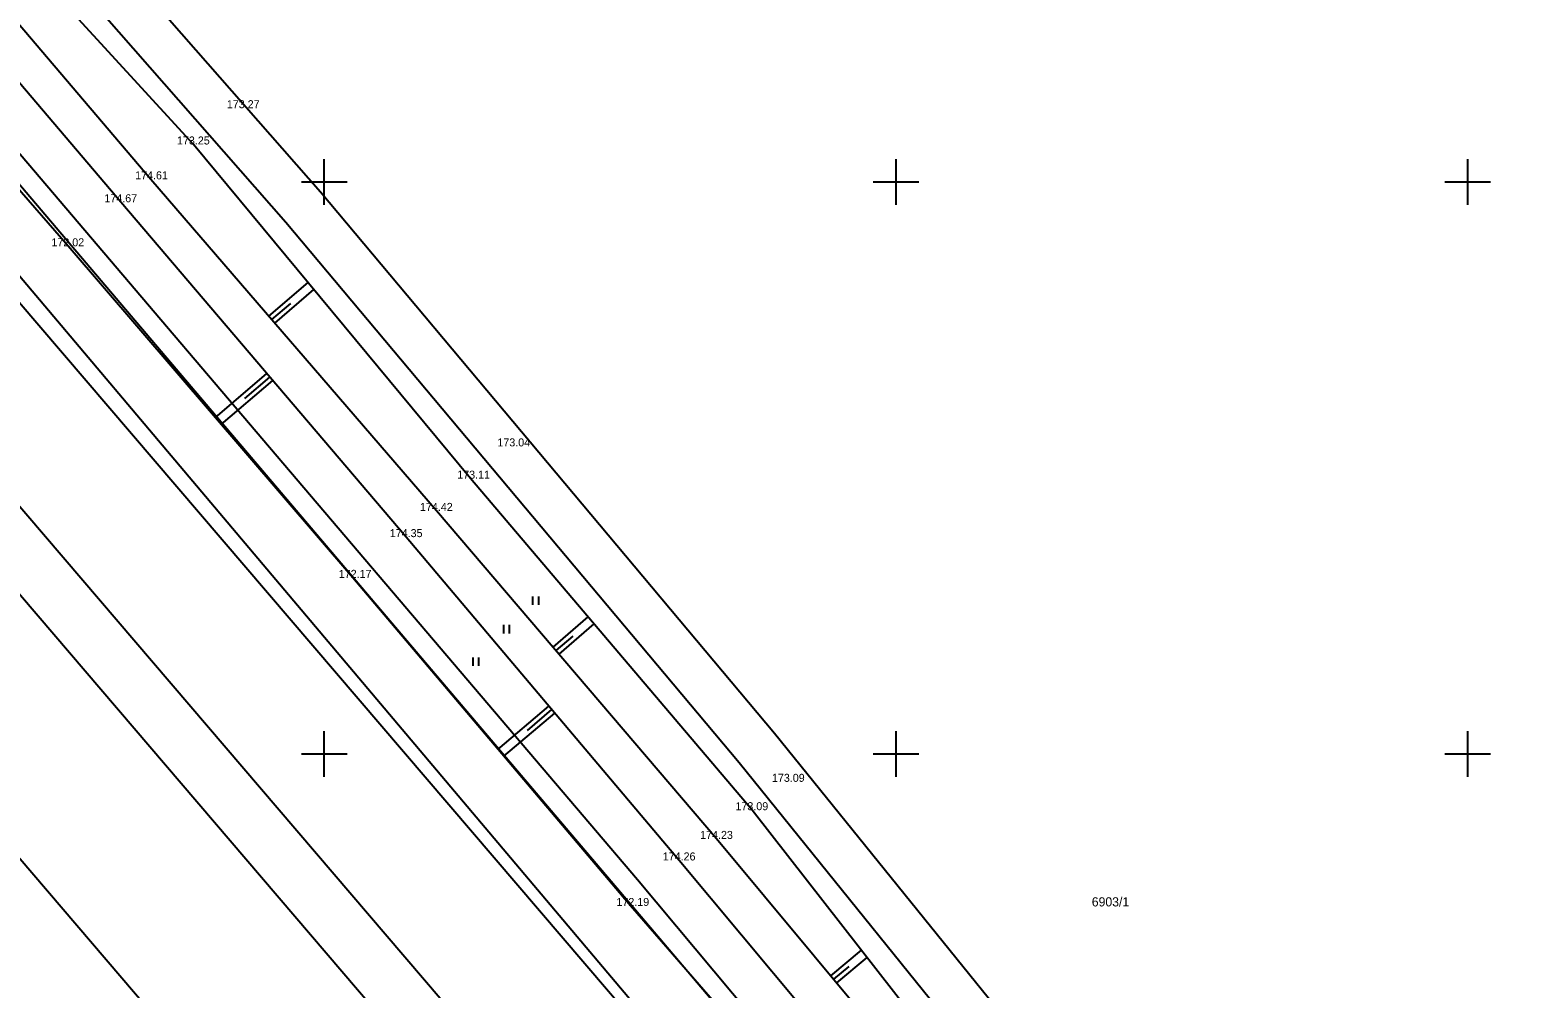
# Model space of a CAD drawing. Extents: x -612546 to -611926, y -1201932 to -1200444.
# Drawn here: x -612225.8 to -612096, y -1201070.5 to -1200986.7 of the extents above; entities that cross this region are included whole.
import ezdxf

# ---------------------------------------------------------------- set-up
doc = ezdxf.new("R2010")
doc.units = 0
for name, color, linetype in [('14 hrana pata svahu', 7, 'Continuous'), ('15 šrafy', 7, 'Continuous'), ('61 legenda křížky', 7, 'Continuous'), ('Hranice parcel', 7, 'Continuous'), ('Parcelní čísla', 7, 'Continuous'), ('Vnitřní kresba', 7, 'Continuous'), ('Vrstva 36', 7, 'Continuous'), ('výška bodu', 7, 'Continuous')]:
    doc.layers.add(name, color=color, linetype=linetype)

msp = doc.modelspace()

# ---------------------------------------------------------------- linework, layer by layer
at = {"layer": '14 hrana pata svahu'}
for points in [[(-612115.84, -1201111.42), (-612142.3, -1201080.92), (-612162.58, -1201054.92), (-612187.22, -1201025.94), (-612211.45, -1200996.73), (-612237.71, -1200968.13), (-612275.47, -1200925.26), (-612297.25, -1200898.18), (-612305.42, -1200888.34), (-612310.59, -1200874.11), (-612323.74, -1200837.38), (-612336.44, -1200801.43), (-612350.12, -1200764.09), (-612361.57, -1200731.35), (-612377.95, -1200692.77), (-612388.38, -1200663.69), (-612401.66, -1200625.89), (-612414.44, -1200590.59), (-612427.78, -1200553.92), (-612436.33, -1200532.1), (-612442.76, -1200519.02), (-612455.83, -1200502.43), (-612463.71, -1200487.36), (-612471.87, -1200478.15)], [(-612103.83, -1201136.8), (-612121.3, -1201116.23), (-612147.17, -1201085.43), (-612168.95, -1201059.31), (-612192.84, -1201031.05), (-612217.78, -1201001.78), (-612242.41, -1200972.81), (-612279.4, -1200929.44), (-612302.66, -1200902.78), (-612311.18, -1200891.48), (-612317.69, -1200875.87), (-612330.64, -1200840.25), (-612343.46, -1200803.61), (-612356.83, -1200766.41), (-612369.51, -1200733.46), (-612383.93, -1200694.82), (-612394.68, -1200665.1), (-612407.78, -1200627.56), (-612420.74, -1200592.57), (-612433.93, -1200555.79), (-612441.34, -1200534.1), (-612447.31, -1200522.04), (-612459.97, -1200505.78), (-612472.95, -1200489.44)], [(-612100.62, -1201134.15), (-612118.63, -1201113.83), (-612144.42, -1201082.96), (-612165.7, -1201057.43), (-612190.2, -1201028.76), (-612215.18, -1200999.78), (-612240.07, -1200970.53), (-612277.47, -1200927.11), (-612299.67, -1200900.56), (-612307.52, -1200889.81), (-612314.18, -1200875.11), (-612327.34, -1200838.97)], [(-612083.4, -1201170.96), (-612107.88, -1201140.83), (-612125.72, -1201119.76), (-612151.16, -1201088.66), (-612173.22, -1201063.29), (-612197.5, -1201034.61), (-612222.4, -1201005.63), (-612247.09, -1200977.25), (-612284.99, -1200933.95), (-612307.37, -1200907.39), (-612317.17, -1200894.63), (-612323.51, -1200877.98), (-612336.33, -1200841.94)]]:
    msp.add_lwpolyline(points, dxfattribs=at)
at = {"layer": '15 šrafy'}
for p, q in [((-612201.45, -1201008.79), (-612204.87, -1201011.74)), ((-612200.94, -1201009.4), (-612204.35, -1201012.35)), ((-612202.96, -1201010.62), (-612204.61, -1201012.04)), ((-612209.53, -1201020.61), (-612205.01, -1201016.76)), ((-612209.01, -1201021.22), (-612204.5, -1201017.37)), ((-612206.94, -1201018.93), (-612204.75, -1201017.07)), ((-612176.94, -1201038.03), (-612180.02, -1201040.67)), ((-612176.42, -1201038.64), (-612179.5, -1201041.28)), ((-612178.27, -1201039.7), (-612179.76, -1201040.97)), ((-612184.81, -1201049.6), (-612180.35, -1201045.82)), ((-612184.3, -1201050.21), (-612179.83, -1201046.43)), ((-612182.23, -1201047.94), (-612180.09, -1201046.13)), ((-612153.04, -1201067.16), (-612155.72, -1201069.4)), ((-612154.13, -1201068.59), (-612155.47, -1201069.7)), ((-612152.54, -1201067.79), (-612155.21, -1201070.01))]:
    msp.add_line(p, q, dxfattribs=at)
at = {"layer": '61 legenda křížky'}
for p, q in [((-612200, -1201002), (-612200, -1200998)), ((-612150, -1201002), (-612150, -1200998)), ((-612100, -1201002), (-612100, -1200998)), ((-612202, -1201000), (-612198, -1201000)), ((-612152, -1201000), (-612148, -1201000)), ((-612102, -1201000), (-612098, -1201000)), ((-612200, -1201052), (-612200, -1201048)), ((-612150, -1201052), (-612150, -1201048)), ((-612100, -1201052), (-612100, -1201048)), ((-612202, -1201050), (-612198, -1201050)), ((-612152, -1201050), (-612148, -1201050)), ((-612102, -1201050), (-612098, -1201050))]:
    msp.add_line(p, q, dxfattribs=at)
at = {"layer": 'Hranice parcel'}
for points in [[(-612492.54, -1200475.45), (-612489.15, -1200479.9), (-612487.29, -1200482.34), (-612470.55, -1200499.86), (-612454.58, -1200517.89), (-612449.12, -1200526.98), (-612444.88, -1200537.01), (-612400.71, -1200658.68), (-612382.76, -1200708.97), (-612320.94, -1200880.21), (-612316.28, -1200891.06), (-612307.37, -1200903.62), (-612259.67, -1200958.71), (-612214.29, -1201012.03), (-612172.62, -1201060.98), (-612120.7, -1201123.05), (-612073.85, -1201178.4), (-612068.4, -1201184.83), (-612055.42, -1201199.11), (-612044.78, -1201213.9), (-612040.42, -1201224.33), (-612036.87, -1201232.26)], [(-612053.63, -1201234.04), (-612049.72, -1201229.74), (-612051.31, -1201220.57), (-612058.28, -1201208.42), (-612073.89, -1201189.58), (-612079.31, -1201183.16), (-612173.25, -1201072.99), (-612266.53, -1200963.98), (-612308.11, -1200916.05), (-612320.05, -1200901.46), (-612326.37, -1200888.91), (-612352.76, -1200817.26), (-612383.45, -1200732.24), (-612424.46, -1200618.96), (-612450.75, -1200547.77), (-612455.75, -1200534.91), (-612462.05, -1200524.68), (-612490.01, -1200492.58), (-612497.19, -1200482.99)], [(-612504.85, -1200495.41), (-612492.66, -1200506.93), (-612476.27, -1200525), (-612462.43, -1200549.41), (-612435.01, -1200623.69), (-612394.62, -1200736.44), (-612362.83, -1200822.52), (-612336.91, -1200893.7), (-612329.46, -1200906.86), (-612317.29, -1200922.46), (-612274.72, -1200972.15), (-612181.97, -1201080.59), (-612092.56, -1201185.28), (-612096.16, -1201188.77)], [(-612098.55, -1201185.97), (-612185.77, -1201083.84), (-612278.52, -1200975.4), (-612321.16, -1200925.63), (-612333.63, -1200909.64), (-612341.47, -1200895.8), (-612367.52, -1200824.24), (-612399.32, -1200738.15), (-612439.71, -1200625.4), (-612466.98, -1200551.52), (-612480.35, -1200527.95), (-612496.23, -1200510.43), (-612507.54, -1200499.75)], [(-612480.63, -1200557.86), (-612453.81, -1200630.53), (-612413.42, -1200743.28), (-612381.61, -1200829.41), (-612355.13, -1200902.11), (-612346.14, -1200918), (-612332.78, -1200935.12), (-612289.91, -1200985.15), (-612197.17, -1201093.58), (-612109.96, -1201195.71)], [(-612367.63, -1200702.46), (-612366.44, -1200717.27), (-612308.59, -1200877.88), (-612303.27, -1200888.65), (-612292.69, -1200901.79), (-612203.37, -1201003.51), (-612163.72, -1201050.75), (-612139.89, -1201080.24), (-612084.23, -1201147.54), (-612068.31, -1201163.86)], [(-612027.25, -1201146.78), (-612057.59, -1201153.91), (-612067.61, -1201153.97), (-612081.25, -1201144.86), (-612136.79, -1201077.71), (-612160.63, -1201048.21), (-612200.33, -1201000.9), (-612214.59, -1200984.67)]]:
    msp.add_lwpolyline(points, dxfattribs=at)
at = {"layer": 'Vnitřní kresba'}
for p, q in [((-612303.02, -1200910.37), (-612174.91, -1201061.11)), ((-612174.91, -1201061.11), (-612079.46, -1201173.47))]:
    msp.add_line(p, q, dxfattribs=at)
msp.add_lwpolyline([(-612077.99, -1201182.01), (-612172.2, -1201072.72), (-612264.55, -1200963.36), (-612306.48, -1200914.97), (-612319.15, -1200900.26), (-612324.5, -1200887.86), (-612350.35, -1200818.69), (-612381.6, -1200731.97), (-612422.84, -1200618.87), (-612449.81, -1200544.11), (-612465.28, -1200517.45), (-612482.79, -1200495.64), (-612497.19, -1200482.99)], dxfattribs=at)
at = {"layer": 'Vrstva 36'}
for p, q in [((-612181.75, -1201036.98), (-612181.75, -1201036.23)), ((-612181.25, -1201036.98), (-612181.25, -1201036.23)), ((-612184.29, -1201039.47), (-612184.29, -1201038.72)), ((-612183.79, -1201039.47), (-612183.79, -1201038.72)), ((-612186.98, -1201042.31), (-612186.98, -1201041.56)), ((-612186.48, -1201042.31), (-612186.48, -1201041.56))]:
    msp.add_line(p, q, dxfattribs=at)

# ---------------------------------------------------------------- texts
at = {"layer": 'Parcelní čísla'}
msp.add_text('6903/1', height=0.8, dxfattribs=at).set_placement((-612132.88, -1201063.33))
at = {"layer": 'výška bodu'}
for s, p in [('173.27', (-612208.52, -1200993.56)), ('173.25', (-612212.88, -1200996.73)), ('174.61', (-612216.54, -1200999.78)), ('174.67', (-612219.23, -1201001.78)), ('172.02', (-612223.86, -1201005.63)), ('173.04', (-612184.86, -1201023.12)), ('173.11', (-612188.37, -1201025.94)), ('174.42', (-612191.63, -1201028.76)), ('174.35', (-612194.27, -1201031.05)), ('172.17', (-612198.73, -1201034.61)), ('173.09', (-612160.85, -1201052.44)), ('173.09', (-612164.04, -1201054.92)), ('174.23', (-612167.13, -1201057.43)), ('174.26', (-612170.4, -1201059.31)), ('172.19', (-612174.45, -1201063.29))]:
    msp.add_text(s, height=0.7, dxfattribs=at).set_placement(p)

doc.saveas('drawing.dxf')
